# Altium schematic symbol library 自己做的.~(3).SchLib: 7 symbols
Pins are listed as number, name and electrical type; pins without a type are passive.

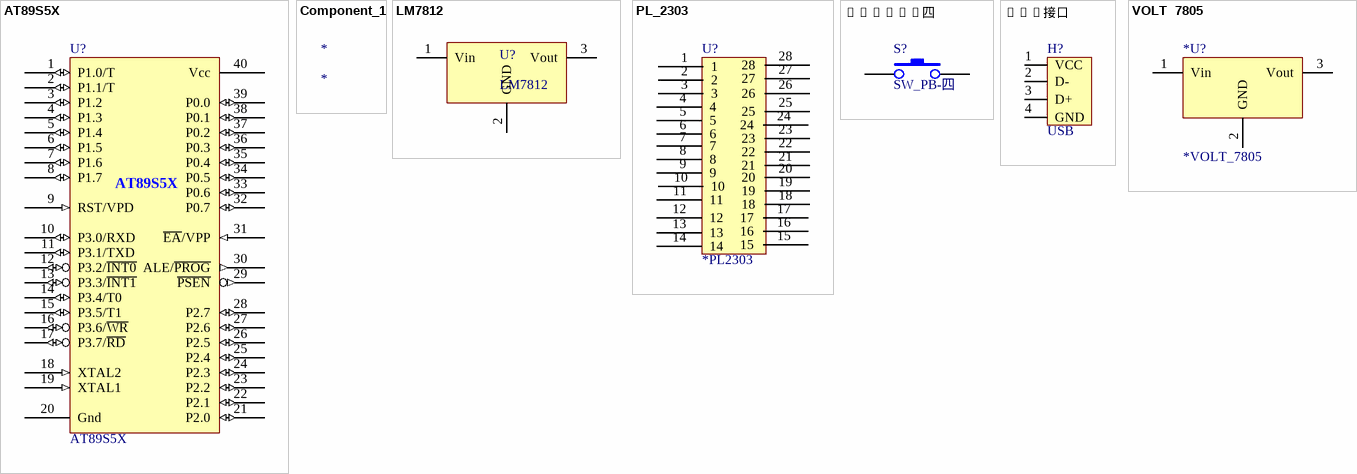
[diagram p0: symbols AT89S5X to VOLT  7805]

## AT89S5X
designator U?
footprint DIP40
pins: 1 P1.0/T (io), 2 P1.1/T (io), 3 P1.2 (io), 4 P1.3 (io), 5 P1.4 (io), 6 P1.5 (io), 7 P1.6 (io), 8 P1.7 (io), 9 RST/VPD (in), 10 P3.0/RXD (io), 11 P3.1/TXD (io), 12 P3.2/~{INT0} (io), 13 P3.3/~{INT1} (io), 14 P3.4/T0 (io), 15 P3.5/T1 (io), 16 P3.6/~{WR} (io), 17 P3.7/~{RD} (io), 18 XTAL2 (in), 19 XTAL1 (in), 20 Gnd (power), 21 P2.0 (io), 22 P2.1 (io), 23 P2.2 (io), 24 P2.3 (io), 25 P2.4 (io), 26 P2.5 (io), 27 P2.6 (io), 28 P2.7 (io), 29 ~{PSEN} (out), 30 ALE/~{PROG} (out), 31 ~{EA}/VPP (in), 32 P0.7 (io), 33 P0.6 (io), 34 P0.5 (io), 35 P0.4 (io), 36 P0.3 (io), 37 P0.2 (io), 38 P0.1 (io), 39 P0.0 (io), 40 Vcc (power)

## Component_1
designator *

## LM7812
designator U?
footprint VR5
pins: 1 Vin, 2 GND, 3 Vout

## PL_2303
designator U?, comment *PL2303
footprint PL_2303
pins: 1, 2, 3, 4, 5, 6, 7, 8, 9, 10, 11, 12, 13, 14, 15, 16, 17, 18, 19, 20, 21, 22, 23, 24, 25, 26, 27, 28

## SW_PB-四
designator S?
footprint B键
pins: 1, 2

## USB接口
designator H?, comment USB
footprint USB接口 (usb接口)
pins: 1 VCC, 2 D-, 3 D+, 4 GND

## VOLT  7805
designator *U?, comment *VOLT_7805
footprint VOLT_7805
pins: 1 Vin, 2 GND, 3 Vout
